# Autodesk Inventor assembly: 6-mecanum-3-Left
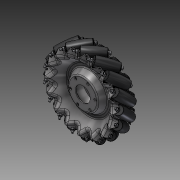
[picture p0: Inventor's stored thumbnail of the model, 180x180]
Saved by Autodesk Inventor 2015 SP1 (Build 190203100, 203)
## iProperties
Created: 2015-01
Part Number: 6-mecanum-3-Left
Document SubType Name: Assembly
Designer: TODD D MILLER
Mass: 589.67 g
Surface Area: 1360.11 cm^2
Volume: 181.889 cm^3
Density: 3.24192 g/cm^3
Title: 6-mecanum-3-Left.STEP
Description: STEP AP203
Creation Date: 2010-12-06
Sending System: SolidWorks 2010
Preprocessor: SwSTEP 2.0
Author: TODD D MILLER
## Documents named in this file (5)
- C:\Users\TODD D MILLER\Documents\GrabCAD\ElkLogics FRC\CAD Library\Mecanum wheels\6-mecanum-3-Left.iam
- C:\Users\TODD D MILLER\Documents\GrabCAD\ElkLogics FRC\CAD Library\Mecanum wheels\6-mecanum-3-Right\1_6.ipt
- C:\Users\TODD D MILLER\Documents\GrabCAD\ElkLogics FRC\CAD Library\Mecanum wheels\6-mecanum-3-Right\M - 3 x 0.5 x 50 SHCS_M - 3 x 0.5 x 50 SHCS.ipt
- C:\Users\TODD D MILLER\Documents\GrabCAD\ElkLogics FRC\CAD Library\Mecanum wheels\6-mecanum-3-Right\M3-Nylock-Nut_2.ipt
- C:\Users\TODD D MILLER\Documents\GrabCAD\ElkLogics FRC\CAD Library\Mecanum wheels\6-mecanum-3-Right\6 mecanum plate 3.ipt
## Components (50 placed, 50 different names)
1. 1_6_1
2. 1_6_2
3. M - 3 x 0.5 x 50 SHCS_M - 3 x 0.5 x 50 SHCS_3
4. 1_6_4
5. 1_6_5
6. M3-Nylock-Nut_2_6
7. 1_6_7
8. M3-Nylock-Nut_2_8
9. M - 3 x 0.5 x 50 SHCS_M - 3 x 0.5 x 50 SHCS_9
10. 1_6_10
11. M3-Nylock-Nut_2_11
12. M - 3 x 0.5 x 50 SHCS_M - 3 x 0.5 x 50 SHCS_12
13. M3-Nylock-Nut_2_13
14. M3-Nylock-Nut_2_14
15. M3-Nylock-Nut_2_15
16. M - 3 x 0.5 x 50 SHCS_M - 3 x 0.5 x 50 SHCS_16
17. M3-Nylock-Nut_2_17
18. M - 3 x 0.5 x 50 SHCS_M - 3 x 0.5 x 50 SHCS_18
19. 6 mecanum plate 3_19
20. 1_6_20
21. M3-Nylock-Nut_2_21
22. 1_6_22
23. M3-Nylock-Nut_2_23
24. 1_6_24
25. 1_6_25
26. M3-Nylock-Nut_2_26
27. M - 3 x 0.5 x 50 SHCS_M - 3 x 0.5 x 50 SHCS_27
28. M - 3 x 0.5 x 50 SHCS_M - 3 x 0.5 x 50 SHCS_28
29. 1_6_29
30. M3-Nylock-Nut_2_30
31. M - 3 x 0.5 x 50 SHCS_M - 3 x 0.5 x 50 SHCS_31
32. 6 mecanum plate 3_32
33. 1_6_33
34. M - 3 x 0.5 x 50 SHCS_M - 3 x 0.5 x 50 SHCS_34
35. M - 3 x 0.5 x 50 SHCS_M - 3 x 0.5 x 50 SHCS_35
36. M - 3 x 0.5 x 50 SHCS_M - 3 x 0.5 x 50 SHCS_36
37. M3-Nylock-Nut_2_37
38. M - 3 x 0.5 x 50 SHCS_M - 3 x 0.5 x 50 SHCS_38
39. 1_6_39
40. M3-Nylock-Nut_2_40
41. M3-Nylock-Nut_2_41
42. M - 3 x 0.5 x 50 SHCS_M - 3 x 0.5 x 50 SHCS_42
43. 1_6_43
44. M3-Nylock-Nut_2_44
45. M - 3 x 0.5 x 50 SHCS_M - 3 x 0.5 x 50 SHCS_45
46. M - 3 x 0.5 x 50 SHCS_M - 3 x 0.5 x 50 SHCS_46
47. M - 3 x 0.5 x 50 SHCS_M - 3 x 0.5 x 50 SHCS_47
48. 1_6_48
49. 1_6_49
50. M3-Nylock-Nut_2_50
